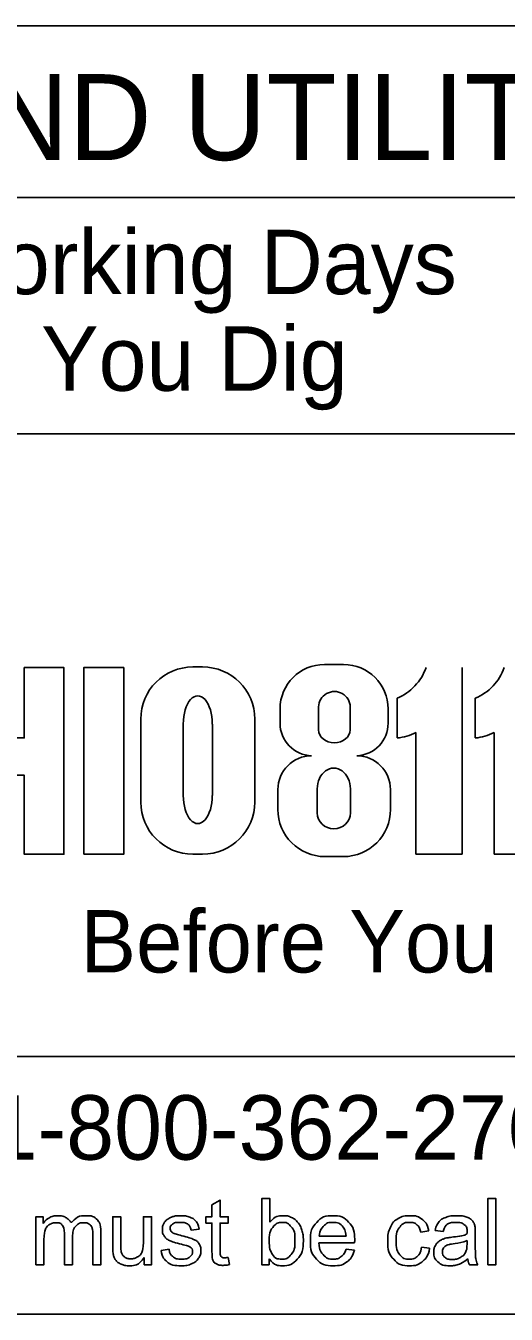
# Model space of a CAD drawing. Extents: x 1862092.2 to 1862141.4, y 420599.8 to 420643.6.
# Drawn here: x 1862102.209 to 1862103.327, y 420603.351 to 420606.351 of the extents above; entities that cross this region are included whole.
import ezdxf

# ---------------------------------------------------------------- set-up
doc = ezdxf.new("R2010")
doc.units = 0
doc.layers.add('SH_Data', color=7, linetype='Continuous')

msp = doc.modelspace()

# ---------------------------------------------------------------- linework, layer by layer
at = {"layer": 'SH_Data'}
for p, q in [((1862100.2055, 420606.3508), (1862104.9554, 420606.3508)), ((1862100.2055, 420605.9508), (1862104.9554, 420605.9508)), ((1862100.2055, 420605.4008), (1862104.9554, 420605.4008)), ((1862102.6204, 420604.8578), (1862102.5979, 420604.8578)), ((1862102.9487, 420604.8637), (1862102.9042, 420604.8637)), ((1862103.2248, 420604.8564), (1862103.2248, 420604.4219)), ((1862102.8006, 420604.7601), (1862102.8006, 420604.7271)), ((1862102.8904, 420604.7116), (1862102.8904, 420604.765)), ((1862102.964, 420604.765), (1862102.964, 420604.7116)), ((1862103.0523, 420604.7271), (1862103.0523, 420604.7601)), ((1862103.0732, 420604.6925), (1862103.0732, 420604.7851)), ((1862103.2551, 420604.6925), (1862103.2551, 420604.7851)), ((1862102.4764, 420604.7363), (1862102.4764, 420604.5434)), ((1862102.7419, 420604.5434), (1862102.7419, 420604.7363)), ((1862102.5754, 420604.5589), (1862102.5754, 420604.725)), ((1862102.6431, 420604.725), (1862102.6431, 420604.5589)), ((1862103.1171, 420604.4219), (1862103.1171, 420604.7052)), ((1862103.299, 420604.4219), (1862103.299, 420604.7052)), ((1862102.7956, 420604.5724), (1862102.7956, 420604.5262)), ((1862102.8872, 420604.5181), (1862102.8872, 420604.5737)), ((1862102.9644, 420604.5737), (1862102.9644, 420604.5181)), ((1862103.0578, 420604.5262), (1862103.0578, 420604.5724)), ((1862102.5979, 420604.4219), (1862102.6204, 420604.4219)), ((1862102.9055, 420604.4163), (1862102.9479, 420604.4163)), ((1862103.2248, 420604.4219), (1862103.1171, 420604.4219)), ((1862103.4067, 420604.4219), (1862103.299, 420604.4219)), ((1862104.9554, 420603.9508), (1862100.2055, 420603.9508)), ((1862104.9554, 420603.3508), (1862100.2055, 420603.3508))]:
    msp.add_line(p, q, dxfattribs=at)
for points in [[(1862102.136, 420604.6056), (1862102.2052, 420604.6056), (1862102.2052, 420604.4219), (1862102.2975, 420604.4219), (1862102.2975, 420604.8564), (1862102.2052, 420604.8564), (1862102.2052, 420604.6925), (1862102.136, 420604.6925), (1862102.136, 420604.8564)], [(1862102.3436, 420604.4219), (1862102.437, 420604.4219), (1862102.437, 420604.8564), (1862102.3436, 420604.8564), (1862102.3436, 420604.4219)], [(1862102.8742, 420604.6511), (1862102.8742, 420604.651)], [(1862102.9792, 420604.651), (1862102.9792, 420604.6511)], [(1862102.6422, 420603.4988), (1862102.6422, 420603.5631), (1862102.6283, 420603.5631), (1862102.6283, 420603.5777), (1862102.6422, 420603.5777), (1862102.6422, 420603.6054), (1862102.6611, 420603.6167), (1862102.6611, 420603.5777), (1862102.68, 420603.5777), (1862102.68, 420603.5631), (1862102.6611, 420603.5631), (1862102.6611, 420603.4977)], [(1862102.7757, 420603.4661), (1862102.7582, 420603.4661), (1862102.7582, 420603.6201), (1862102.7771, 420603.6201), (1862102.7771, 420603.5652)], [(1862103.2841, 420603.4661), (1862103.2841, 420603.6201), (1862103.303, 420603.6201), (1862103.303, 420603.4661), (1862103.2841, 420603.4661)], [(1862102.2323, 420603.4661), (1862102.2323, 420603.5777), (1862102.2492, 420603.5777), (1862102.2492, 420603.562)], [(1862102.4111, 420603.5086), (1862102.4111, 420603.5777), (1862102.43, 420603.5777), (1862102.43, 420603.5159)], [(1862102.4826, 420603.518), (1862102.4826, 420603.5777), (1862102.5015, 420603.5777), (1862102.5015, 420603.4661), (1862102.4846, 420603.4661)], [(1862102.3175, 420603.5309), (1862102.3175, 420603.4661), (1862102.2986, 420603.4661), (1862102.2986, 420603.5386)], [(1862102.3836, 420603.5427), (1862102.3836, 420603.4661), (1862102.3647, 420603.4661), (1862102.3647, 420603.5364)], [(1862102.6122, 420603.5489), (1862102.5936, 420603.5464)], [(1862102.8921, 420603.5326), (1862102.9545, 420603.5326)], [(1862103.147, 420603.5449), (1862103.1285, 420603.5421)], [(1862103.1803, 420603.5434), (1862103.1617, 420603.5458)], [(1862103.2552, 420603.5381), (1862103.2552, 420603.5129)], [(1862102.2512, 420603.524), (1862102.2512, 420603.4661), (1862102.2323, 420603.4661)], [(1862102.5236, 420603.4995), (1862102.5422, 420603.5024)], [(1862102.9743, 420603.5171), (1862102.8911, 420603.5171)], [(1862102.9542, 420603.5022), (1862102.9738, 420603.4997)], [(1862103.1302, 420603.507), (1862103.1487, 420603.5045)], [(1862103.2361, 420603.5152), (1862103.2362, 420603.5221)], [(1862102.4846, 420603.4661), (1862102.4846, 420603.4826)], [(1862102.68, 420603.483), (1862102.6827, 420603.4663)], [(1862102.7757, 420603.4801), (1862102.7757, 420603.4661)], [(1862103.2612, 420603.4661), (1862103.2414, 420603.4661)]]:
    msp.add_lwpolyline(points, dxfattribs=at)
for centre, radius, start, end in [((1862102.5979, 420604.7363), 0.1215, 90, 180), ((1862102.6204, 420604.7363), 0.1215, 0, 90), ((1862102.9042, 420604.7601), 0.1036, 90, 180), ((1862102.9487, 420604.7601), 0.1036, 0, 90), ((1862103.0271, 420604.8961), 0.1202, 292.5572, 340.7355), ((1862103.2091, 420604.8961), 0.1202, 292.5572, 340.7355), ((1862102.8766, 420604.7271), 0.076, 180, 268.1442), ((1862102.9763, 420604.7271), 0.076, 272.2058, 0), ((1862103.0624, 420604.8122), 0.1202, 275.1733, 297.0931), ((1862103.2443, 420604.8122), 0.1202, 275.1733, 297.0931), ((1862102.8742, 420604.5724), 0.0786, 90, 180), ((1862102.9792, 420604.5724), 0.0786, 0, 90), ((1862102.5979, 420604.5434), 0.1215, 180, 270), ((1862102.6204, 420604.5434), 0.1215, 270, 0), ((1862102.9055, 420604.5262), 0.1099, 180, 270), ((1862102.9479, 420604.5262), 0.1099, 270, 0)]:
    msp.add_arc(centre, radius, start, end, dxfattribs=at)
for centre, major_axis, ratio, start_param, end_param in [((1862102.6092, 420604.725), (0, 0.0657), 0.514403, 4.712389, 7.853982), ((1862102.9272, 420604.765), (0.0368, 0), 0.969373, 0, 3.141593), ((1862102.9272, 420604.7116), (0.0368, 0), 0.818453, 3.141593, 6.283185), ((1862102.9258, 420604.5737), (0, 0.0486), 0.794529, 4.712389, 7.853982), ((1862102.6092, 420604.5589), (0, 0.0657), 0.514403, 1.570796, 4.712389), ((1862102.9258, 420604.5181), (0.0386, 0), 0.959837, 3.141593, 6.283185)]:
    msp.add_ellipse(centre, major_axis=major_axis, ratio=ratio, start_param=start_param, end_param=end_param, dxfattribs=at)
for points, degree in [([(1862102.2492, 420603.562), (1862102.2545, 420603.5702), (1862102.2632, 420603.5752), (1862102.2719, 420603.5802), (1862102.2831, 420603.5802), (1862102.2955, 420603.5802), (1862102.3034, 420603.5751), (1862102.3113, 420603.5699), (1862102.3146, 420603.5606), (1862102.3279, 420603.5802), (1862102.3491, 420603.5802), (1862102.3657, 420603.5802), (1862102.3747, 420603.571), (1862102.3836, 420603.5618), (1862102.3836, 420603.5427)], 3), ([(1862102.2986, 420603.5386), (1862102.2986, 420603.5512), (1862102.294, 420603.5575), (1862102.2894, 420603.5638), (1862102.2789, 420603.5638), (1862102.2709, 420603.5638), (1862102.2641, 420603.5596), (1862102.2573, 420603.5554), (1862102.2543, 420603.5473), (1862102.2512, 420603.5392), (1862102.2512, 420603.524)], 3), ([(1862102.3647, 420603.5364), (1862102.3647, 420603.5477), (1862102.3629, 420603.5527), (1862102.3611, 420603.5577), (1862102.3562, 420603.5607), (1862102.3514, 420603.5638), (1862102.3449, 420603.5638), (1862102.3331, 420603.5638), (1862102.3253, 420603.556), (1862102.3175, 420603.5481), (1862102.3175, 420603.5309)], 3), ([(1862102.5936, 420603.5464), (1862102.5924, 420603.555), (1862102.5863, 420603.5599), (1862102.5803, 420603.5647), (1862102.5692, 420603.5647), (1862102.5562, 420603.5647), (1862102.5506, 420603.5604), (1862102.545, 420603.5561), (1862102.545, 420603.5503), (1862102.545, 420603.5466), (1862102.5474, 420603.5437), (1862102.5497, 420603.5406), (1862102.5546, 420603.5386), (1862102.5575, 420603.5376), (1862102.5713, 420603.5338), (1862102.5914, 420603.5284), (1862102.5994, 420603.525), (1862102.6073, 420603.5216), (1862102.6119, 420603.5151), (1862102.6164, 420603.5086), (1862102.6164, 420603.4989), (1862102.6164, 420603.4895), (1862102.6109, 420603.4811), (1862102.6054, 420603.4728), (1862102.5949, 420603.4682), (1862102.5845, 420603.4637), (1862102.5714, 420603.4637), (1862102.5496, 420603.4637), (1862102.5381, 420603.4727), (1862102.5267, 420603.4817), (1862102.5236, 420603.4995)], 3), ([(1862102.5422, 420603.5024), (1862102.5438, 420603.4911), (1862102.551, 420603.4851), (1862102.5582, 420603.4791), (1862102.5712, 420603.4791), (1862102.5843, 420603.4791), (1862102.5906, 420603.4845), (1862102.5969, 420603.4898), (1862102.5969, 420603.4969), (1862102.5969, 420603.5033), (1862102.5913, 420603.507), (1862102.5874, 420603.5096), (1862102.572, 420603.5134), (1862102.5511, 420603.5187), (1862102.5431, 420603.5225), (1862102.535, 420603.5264), (1862102.5309, 420603.5331), (1862102.5267, 420603.5399), (1862102.5267, 420603.5481), (1862102.5267, 420603.5555), (1862102.5302, 420603.5619), (1862102.5336, 420603.5682), (1862102.5395, 420603.5724), (1862102.5439, 420603.5757), (1862102.5515, 420603.578), (1862102.5591, 420603.5802), (1862102.5679, 420603.5802), (1862102.581, 420603.5802), (1862102.591, 420603.5764), (1862102.6009, 420603.5726), (1862102.6057, 420603.5662), (1862102.6104, 420603.5597), (1862102.6122, 420603.5489)], 3), ([(1862102.7755, 420603.5228), (1862102.7755, 420603.5027), (1862102.7809, 420603.4938), (1862102.7898, 420603.4791), (1862102.805, 420603.4791), (1862102.8174, 420603.4791), (1862102.8264, 420603.4899), (1862102.8354, 420603.5007), (1862102.8354, 420603.522), (1862102.8354, 420603.5439), (1862102.8268, 420603.5543), (1862102.8181, 420603.5647), (1862102.8059, 420603.5647), (1862102.7935, 420603.5647), (1862102.7845, 420603.5539), (1862102.7755, 420603.5432), (1862102.7755, 420603.5228)], 3), ([(1862102.7771, 420603.5652), (1862102.7891, 420603.5802), (1862102.8077, 420603.5802), (1862102.818, 420603.5802), (1862102.8271, 420603.5761), (1862102.8363, 420603.5719), (1862102.8423, 420603.5644), (1862102.8482, 420603.5569), (1862102.8516, 420603.5463), (1862102.8549, 420603.5357), (1862102.8549, 420603.5236), (1862102.8549, 420603.4949), (1862102.8407, 420603.4793), (1862102.8266, 420603.4637), (1862102.8067, 420603.4637), (1862102.7869, 420603.4637), (1862102.7757, 420603.4801)], 3), ([(1862102.9738, 420603.4997), (1862102.9692, 420603.4826), (1862102.9567, 420603.4731), (1862102.9442, 420603.4637), (1862102.9247, 420603.4637), (1862102.9003, 420603.4637), (1862102.8859, 420603.4787), (1862102.8716, 420603.4938), (1862102.8716, 420603.521), (1862102.8716, 420603.5491), (1862102.8861, 420603.5647), (1862102.9006, 420603.5802), (1862102.9237, 420603.5802), (1862102.9461, 420603.5802), (1862102.9602, 420603.565), (1862102.9744, 420603.5497), (1862102.9744, 420603.5221), (1862102.9744, 420603.5204), (1862102.9743, 420603.5171)], 3), ([(1862102.9545, 420603.5326), (1862102.9532, 420603.5467), (1862102.9473, 420603.5538), (1862102.9383, 420603.5647), (1862102.9239, 420603.5647), (1862102.9108, 420603.5647), (1862102.902, 420603.556), (1862102.8931, 420603.5472), (1862102.8921, 420603.5326)], 3), ([(1862103.1487, 420603.5045), (1862103.1457, 420603.4853), (1862103.1331, 420603.4745), (1862103.1206, 420603.4637), (1862103.1023, 420603.4637), (1862103.0794, 420603.4637), (1862103.0655, 420603.4786), (1862103.0515, 420603.4936), (1862103.0515, 420603.5215), (1862103.0515, 420603.5396), (1862103.0575, 420603.5531), (1862103.0635, 420603.5667), (1862103.0758, 420603.5734), (1862103.088, 420603.5802), (1862103.1024, 420603.5802), (1862103.1206, 420603.5802), (1862103.1321, 420603.571), (1862103.1437, 420603.5618), (1862103.147, 420603.5449)], 3), ([(1862103.1285, 420603.5421), (1862103.1259, 420603.5533), (1862103.1192, 420603.559), (1862103.1126, 420603.5647), (1862103.1031, 420603.5647), (1862103.0889, 420603.5647), (1862103.0799, 420603.5545), (1862103.071, 420603.5442), (1862103.071, 420603.522), (1862103.071, 420603.4995), (1862103.0796, 420603.4893), (1862103.0882, 420603.4791), (1862103.1021, 420603.4791), (1862103.1133, 420603.4791), (1862103.1207, 420603.486), (1862103.1282, 420603.4928), (1862103.1302, 420603.507)], 3), ([(1862103.2377, 420603.4799), (1862103.2271, 420603.471), (1862103.2174, 420603.4673), (1862103.2077, 420603.4637), (1862103.1966, 420603.4637), (1862103.1782, 420603.4637), (1862103.1683, 420603.4726), (1862103.1585, 420603.4816), (1862103.1585, 420603.4956), (1862103.1585, 420603.5037), (1862103.1622, 420603.5105), (1862103.1659, 420603.5173), (1862103.172, 420603.5214), (1862103.178, 420603.5255), (1862103.1856, 420603.5276), (1862103.1911, 420603.529), (1862103.2024, 420603.5304), (1862103.2252, 420603.5331), (1862103.2361, 420603.5369), (1862103.2362, 420603.5408), (1862103.2362, 420603.5418), (1862103.2362, 420603.5534), (1862103.2308, 420603.5582), (1862103.2236, 420603.5646), (1862103.2093, 420603.5646), (1862103.196, 420603.5646), (1862103.1897, 420603.5599), (1862103.1833, 420603.5552), (1862103.1803, 420603.5434)], 3), ([(1862103.1617, 420603.5458), (1862103.1643, 420603.5577), (1862103.17, 420603.565), (1862103.1758, 420603.5723), (1862103.1867, 420603.5763), (1862103.1977, 420603.5802), (1862103.212, 420603.5802), (1862103.2263, 420603.5802), (1862103.2352, 420603.5768), (1862103.2442, 420603.5735), (1862103.2484, 420603.5684), (1862103.2526, 420603.5633), (1862103.2542, 420603.5555), (1862103.2552, 420603.5507), (1862103.2552, 420603.5381)], 3), ([(1862102.4846, 420603.4826), (1862102.4716, 420603.4637), (1862102.4492, 420603.4637), (1862102.4394, 420603.4637), (1862102.4308, 420603.4674), (1862102.4222, 420603.4712), (1862102.4181, 420603.4769), (1862102.4139, 420603.4827), (1862102.4123, 420603.491), (1862102.4111, 420603.4965), (1862102.4111, 420603.5086)], 3), ([(1862102.43, 420603.5159), (1862102.43, 420603.5011), (1862102.4312, 420603.4959), (1862102.433, 420603.4885), (1862102.4387, 420603.4842), (1862102.4445, 420603.48), (1862102.453, 420603.48), (1862102.4615, 420603.48), (1862102.469, 420603.4843), (1862102.4764, 420603.4887), (1862102.4795, 420603.4962), (1862102.4826, 420603.5037), (1862102.4826, 420603.518)], 3), ([(1862102.6827, 420603.4663), (1862102.6748, 420603.4646), (1862102.6685, 420603.4646), (1862102.6582, 420603.4646), (1862102.6525, 420603.4679), (1862102.6468, 420603.4711), (1862102.6445, 420603.4764), (1862102.6422, 420603.4817), (1862102.6422, 420603.4988)], 3), ([(1862102.6611, 420603.4977), (1862102.6611, 420603.4896), (1862102.6621, 420603.4873), (1862102.6631, 420603.4849), (1862102.6654, 420603.4836), (1862102.6676, 420603.4822), (1862102.6718, 420603.4822), (1862102.6749, 420603.4822), (1862102.68, 420603.483)], 3), ([(1862102.8911, 420603.5171), (1862102.8921, 420603.4987), (1862102.9015, 420603.4889), (1862102.9108, 420603.4791), (1862102.9248, 420603.4791), (1862102.9352, 420603.4791), (1862102.9426, 420603.4846), (1862102.9499, 420603.4901), (1862102.9542, 420603.5022)], 3), ([(1862103.2362, 420603.5221), (1862103.2259, 420603.5179), (1862103.2053, 420603.515), (1862103.1936, 420603.5133), (1862103.1887, 420603.5112), (1862103.1839, 420603.5091), (1862103.1813, 420603.5051), (1862103.1787, 420603.501), (1862103.1787, 420603.4961), (1862103.1787, 420603.4885), (1862103.1844, 420603.4835), (1862103.1901, 420603.4784), (1862103.2011, 420603.4784), (1862103.212, 420603.4784), (1862103.2205, 420603.4832), (1862103.229, 420603.488), (1862103.233, 420603.4963), (1862103.2361, 420603.5027), (1862103.2361, 420603.5152)], 3), ([(1862103.2552, 420603.5129), (1862103.2552, 420603.4865), (1862103.2564, 420603.4795), (1862103.2576, 420603.4725), (1862103.2612, 420603.4661)], 3), ([(1862103.2414, 420603.4661), (1862103.2385, 420603.472), (1862103.2377, 420603.4799)], 2)]:
    msp.add_open_spline(points, degree=degree, dxfattribs=at)

# ---------------------------------------------------------------- texts
for s, height, p in [('UNDERGROUND UTILITIES', 0.2, (1862100.3623, 420606.0381)), ('Contact Two Working Days', 0.15, (1862100.7822, 420605.7259)), ('Before You Dig', 0.15, (1862101.5978, 420605.5009)), ('Before You Dig', 0.1452, (1862102.3359, 420604.1465)), ('OHIO811, 8-1-1, or 1-800-362-2764', 0.15, (1862100.3519, 420603.7106))]:
    msp.add_text(s, height=height, dxfattribs=at).set_placement(p)

doc.saveas('drawing.dxf')
